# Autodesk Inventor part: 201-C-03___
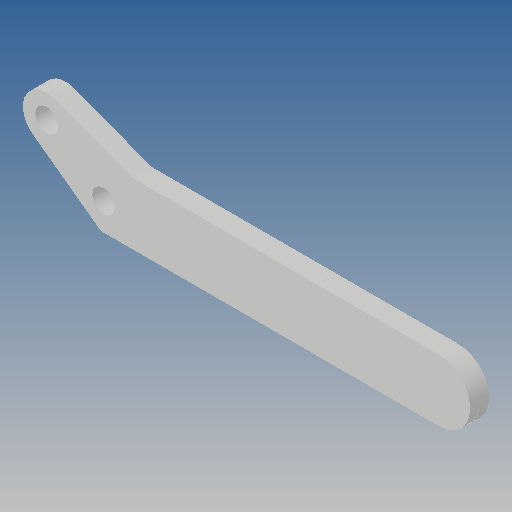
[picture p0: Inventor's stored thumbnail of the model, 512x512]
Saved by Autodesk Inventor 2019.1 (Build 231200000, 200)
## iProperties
Created: 2010-06
Part Number: 201-C-03___
Material: Ogólny
Document SubType Name: Modeling
Designer: CADENGINEERING4
Density: 1 g/cm^3
Appearance: Domyślna
Author: CADENGINEERING4
Revision Number: ANY
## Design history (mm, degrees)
feature "NONE"
feature "NONE:1"
node "Bryła1"
node "Bryła2"
